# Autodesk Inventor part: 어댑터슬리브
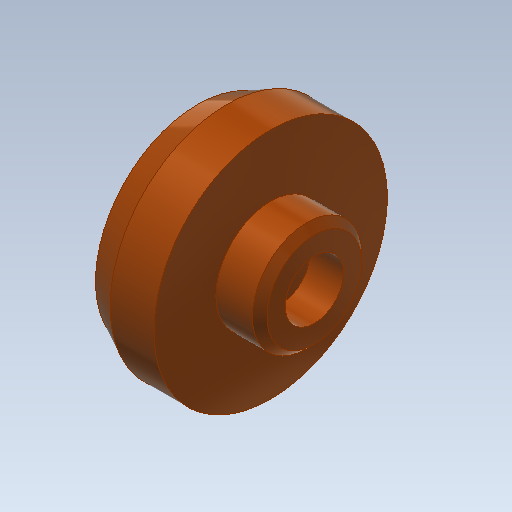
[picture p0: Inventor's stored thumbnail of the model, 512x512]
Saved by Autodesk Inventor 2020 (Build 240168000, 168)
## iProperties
Created: 2016-06
Part Number: 어댑터슬리브
Material: 강철, 탄소
Document SubType Name: Modeling
Designer: mduedu
Density: 7.87 g/cm^3
Appearance: 매끄러움 - 연한 주황색
Author: mduedu
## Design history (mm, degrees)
sketch "스케치2"
  geometry: L1 (0, 0)-(0, 14); L2 (0, 14)-(-4, 16); L3 (-4, 16)-(-10, 16); L4 (-10, 16)-(-10, 7.5); L5 (-10, 7.5)-(-16, 7.5); L6 (-16, 7.5)-(-16, 0); L7 (-16, 0)-(0, 0)
  constraints: 14 end point, 4 parallel, 1 perpendicular, 1 vertical
  dimensions: "d0" = 32 diameter of L3 L7; "d2" = 28 diameter of L1.end L7; "d3" = 6 distance of L2.end L3.end; "d4" = 6 distance of L4.end L5.end; "d5" = 15 diameter of L5 L7; "d6" = 16 distance between parallel lines of L6 L1
revolve "회전1" sketch "스케치2" stored, may be unused: angle "d7" = 90 deg
sketch "스케치3"
  geometry: L1 (-16, -7.5)-(-16, 7.5) reference; L2 (-16, 7.5)-(-10, 7.5) reference; L3 (-10, 7.5)-(-10, 16) reference; L4 (-10, 16)-(-4, 16) reference; L5 (-4, 16)-(0, 14) reference; L6 (0, 14)-(0, -14) reference; L7 (0, -14)-(-4, -16) reference; L8 (-4, -16)-(-10, -16) reference; L9 (-10, -16)-(-10, -7.5) reference; L10 (-10, -7.5)-(-16, -7.5) reference; L11 (0, 10)-(-5, 10); L12 (-5, 10)-(-5, 8); L13 (-5, 8)-(-7, 6); L14 (-7, 6)-(-7, 0); L15 (-7, 0)-(0, 0); L16 (0, 10)-(0, 0)
  constraints: 12 end point, 3 parallel, 2 perpendicular, 1 point on line
  dimensions: "d8" = 20 diameter of L11 L15; "d10" = 16 diameter of L12.end L15; "d11" = 12 diameter of L13.end L15; "d12" = 9 distance between parallel lines of L14 L1; "d13" = 2 distance between parallel lines of L12 L14
revolve "회전2" sketch "스케치3" stored, may be unused: angle "d14" = 90 deg
chamfer "모따기1" distance "d15" = 1; stored, may be unused: second distance "d16" = 2, angle "d17" = 45 deg
sketch "스케치4"
  geometry: 2 further points
  constraints: 1 coincident
sketch "스케치5"
  geometry: 1 further point
hole "구멍1" sketch "스케치5" at (0, 0) diameter "d18" = 4.5; stored, may be unused: countersink angle "d22" = 90 deg, drill point angle "d24" = 0 deg; dims "d19" = 6, "d20" = 8, "d21" = 4.6, "d23" = 8
node "솔리드1"
node "절단 모서리 투영1"
